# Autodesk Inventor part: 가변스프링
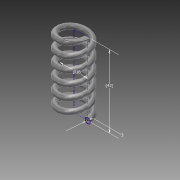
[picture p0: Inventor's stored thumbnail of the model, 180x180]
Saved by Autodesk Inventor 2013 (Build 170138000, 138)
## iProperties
Created: 2015-12
Part Number: 가변스프링
Material: 강철, 탄소
Document SubType Name: Modeling
Designer: Administrator
Density: 7.87 g/cm^3
Mass: 16.5219 g
Surface Area: 28.4696 cm^2
Volume: 2.09936 cm^3
Author: Administrator
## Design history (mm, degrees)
sketch "스케치1"
  geometry: L1 (0, 0)-(-8, 0); L2 (-8, 0)-(-8, 42); L3 (-8, 42)-(0, 42); L4 (0, 42)-(0, 0); C1 r 1.5 at (-8, 0)
  constraints: 8 end point, 2 parallel, 1 centre point, 1 coincident, 1 horizontal, 1 perpendicular
  dimensions: "d0" = 3 diameter of C1; "d2" = 42 distance of L1.end L2.end (derived); "d3" = 16 diameter of L2 L4
feature "코일1" pitch "d4" = 10; turns "d6" = 6; dims "d5" = 42 (= d2), "d7" = 0, angle "d8" = 90 deg, angle "d9" = 90 deg, "d10" = 0, "d11" = 0
sketch "스케치2"
  geometry: L1 (9.5, 0)-(6.5, 0) reference; 1 further point
  constraints: 1 horizontal alignment
extrude "돌출1" cut sketch "스케치2" distance "d12" = 10; taper "d13" = 0 deg
node "작업 평면1"
sketch "스케치3"
  geometry: L1 (-1.5, 0)-(1.5, 0) reference; 1 further point
  constraints: 1 horizontal alignment
extrude "돌출2" cut sketch "스케치3" distance "d15" = 10; taper "d16" = 0 deg
node "솔리드1"
node "절단 모서리 투영1"
node "절단 모서리 투영2"
other parameters: "d14" = 90 deg
